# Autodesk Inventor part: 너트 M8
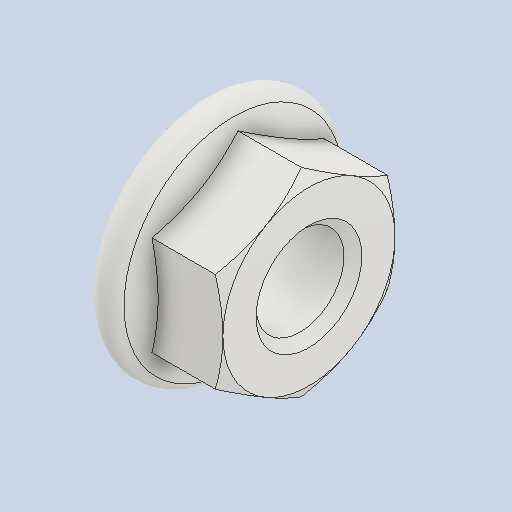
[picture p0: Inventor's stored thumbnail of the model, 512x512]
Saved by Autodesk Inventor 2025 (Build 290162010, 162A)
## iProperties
Created: 2024-07
Part Number: 너트 M8
Material: 스테인리스강
Description: 플랜지붙이 6각 너트 - 일반 스레드
Document SubType Name: Modeling
Designer: Admin
Density: 8 g/cm^3
Appearance: 기본값
Author: jhkim
Sending System: Autodesk Inventor 2025
Preprocessor: ST-DEVELOPER v20
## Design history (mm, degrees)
feature "Solid1"
node "솔리드1"
